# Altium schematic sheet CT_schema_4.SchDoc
size 322 x 302 mm
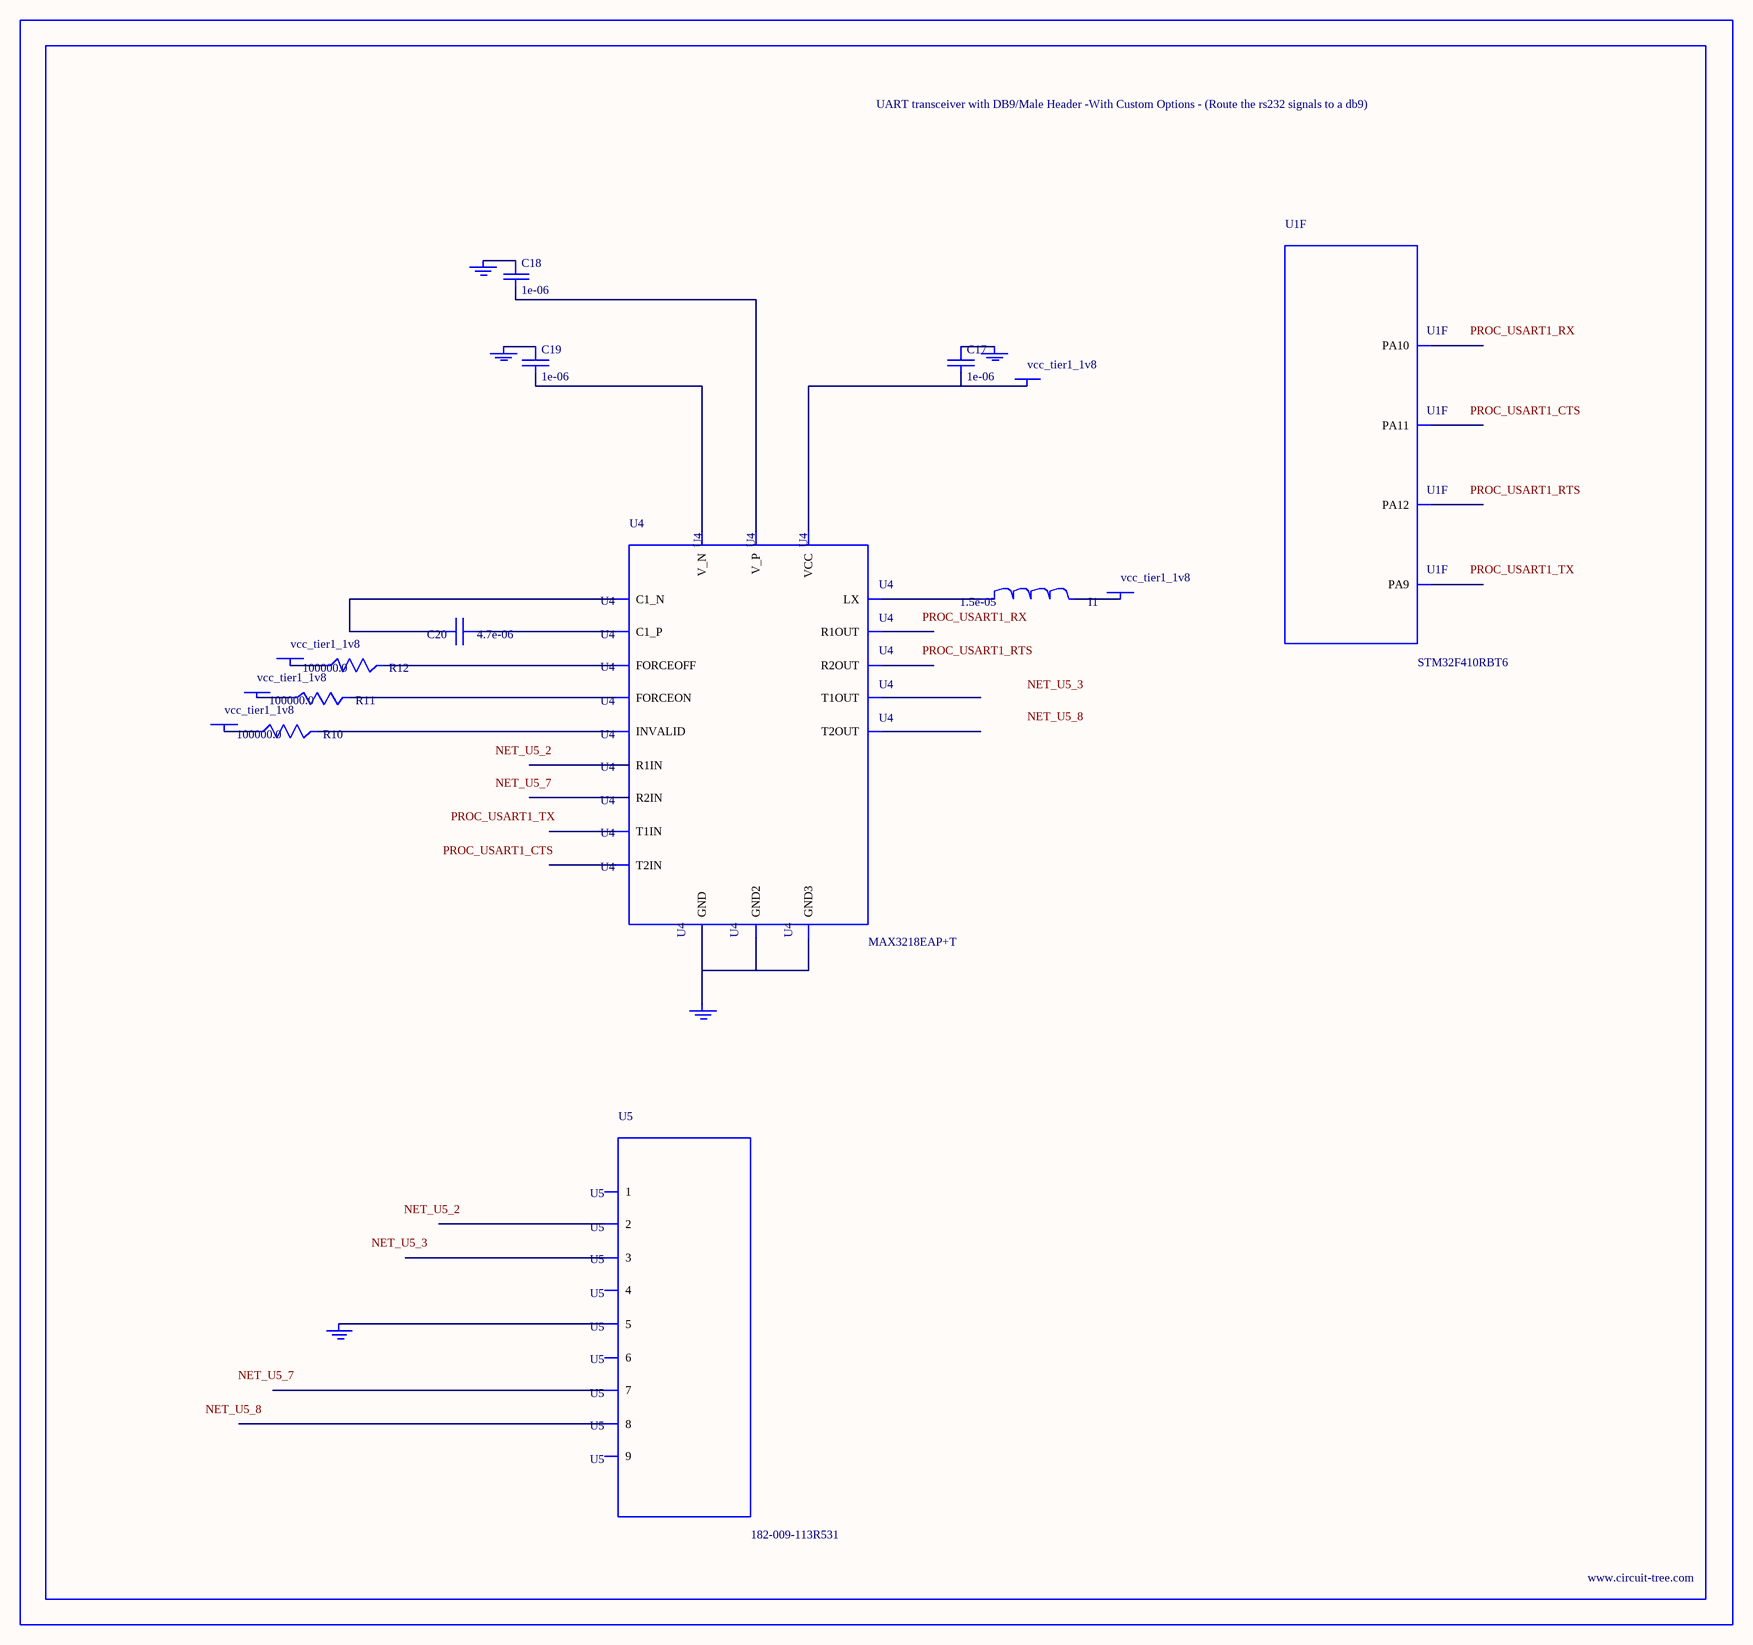
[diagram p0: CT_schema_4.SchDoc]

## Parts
BORDER3  (no value)
C17  1e-06  [C0603]
C18  1e-06  [C0603]
C19  1e-06  [C0603]
C20  4.7e-06  [C0805]
GND_INSTANCE_3_0  (no value)
GND_INSTANCE_3_1  (no value)
GND_INSTANCE_3_2  (no value)
GND_INSTANCE_3_3  (no value)
GND_INSTANCE_3_4  (no value)
I1  1.5e-05  [L1210]
POWER_INSTANCE_3_0  vcc_tier1_1v8
POWER_INSTANCE_3_1  vcc_tier1_1v8
POWER_INSTANCE_3_2  vcc_tier1_1v8
POWER_INSTANCE_3_3  vcc_tier1_1v8
POWER_INSTANCE_3_4  vcc_tier1_1v8
R10  100000.0  [R0603]
R11  100000.0  [R0603]
R12  100000.0  [R0603]
U1  STM32F410RBT6  [LQFP64]  (part F of 6)
U4  MAX3218EAP+T  [SSOP-20]
U5  182-009-113R531  [182-009-MALE]

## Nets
NetC17_1: C17.1 GND_INSTANCE_3_0.0(GND)
NetC17_2: C17.2 POWER_INSTANCE_3_4.0(PWR) U4.6(VCC)
NetC18_1: C18.1 GND_INSTANCE_3_2.0(GND)
NetC18_2: C18.2 U4.19(V_P)
NetC19_1: C19.1 GND_INSTANCE_3_1.0(GND)
NetC19_2: C19.2 U4.15(V_N)
NetC20_1: C20.1 U4.18(C1_P)
NetC20_2: C20.2 U4.16(C1_N)
NetGND_INSTANCE_3_3_0: GND_INSTANCE_3_3.0(GND) U4.5(GND) U4.17(GND2) U4.20(GND3)
NetGND_INSTANCE_3_4_0: GND_INSTANCE_3_4.0(GND) U5.5
NetI1_1: I1.1 U4.1(LX)
NetI1_2: I1.2 POWER_INSTANCE_3_0.0(PWR)
NetPOWER_INSTANCE_3_1_0: POWER_INSTANCE_3_1.0(PWR) R10.1
NetPOWER_INSTANCE_3_2_0: POWER_INSTANCE_3_2.0(PWR) R11.1
NetPOWER_INSTANCE_3_3_0: POWER_INSTANCE_3_3.0(PWR) R12.1
NetR10_2: R10.2 U4.2(INVALID)
NetR11_2: R11.2 U4.3(FORCEON)
NetR12_2: R12.2 U4.4(FORCEOFF)

Not connected (* = marked no-connect by the designer): U1 42(PA9) 43(PA10) 44(PA11) 45(PA12); U4 7(T1IN) 8(T2IN) 9(R1OUT) 10(R2OUT) 11(R2IN) 12(R1IN) 13(T2OUT) 14(T1OUT); U5 1 2 3 4 6 7 8 9

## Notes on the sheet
- Labels drawn without touching a wire or pin: NET_U5_2, NET_U5_3, NET_U5_7, NET_U5_8, PROC_USART1_CTS, PROC_USART1_RTS, PROC_USART1_RX, PROC_USART1_TX

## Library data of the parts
BORDER3 = BORDER_PAGE3
C17-C19 = C0603C105K3RACTU
C20 = C0805C475K4RACTU
GND_INSTANCE_3_0-GND_INSTANCE_3_4 = GND
I1 = L1210R150MDWIT
POWER_INSTANCE_3_0-POWER_INSTANCE_3_4 = PWR
R10-R12 = RC0603JR-07100KL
